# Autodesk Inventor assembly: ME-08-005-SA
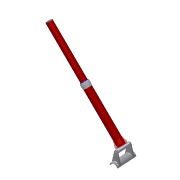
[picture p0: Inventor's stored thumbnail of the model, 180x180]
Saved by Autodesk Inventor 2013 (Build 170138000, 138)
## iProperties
Shininess: 20.0
Length Units: 11269
Angle Units: 11279
Time Units: 11290
Mass Units: 11283
Length Display Precision: 3
Angle Display Precision: 2
Created: 2001-04
Part Number: ME-08-005-SA
Document SubType Name: Baugruppe
Designer: dl
Density: 0.0
Volumn: 0.0
Area: 0.0
PropertySet Name: Model Information
Control State: 0
Master: False
Checked Out: False
Author: dl
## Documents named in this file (14)
- C:\Webworld\Webworld2014\ATC2013\Assemblies\ATC-Baby Carriage\DAMPER\ME-08-005-SA.iam
- C:\Webworld\Webworld2014\ATC2013\Assemblies\ATC-Baby Carriage\DAMPER\Dip_pipe vst.iam
- C:\Webworld\Webworld2014\ATC2013\Assemblies\ATC-Baby Carriage\DAMPER\Spindle vst.iam
- C:\Webworld\Webworld2014\ATC2013\Assemblies\ATC-Baby Carriage\DAMPER\Seam.ipt
- C:\Webworld\Webworld2014\ATC2013\Assemblies\ATC-Baby Carriage\DAMPER\DIN 912 - M5 x 25.ipt
- C:\Webworld\Webworld2014\ATC2013\Assemblies\ATC-Baby Carriage\DAMPER\Spacer_wide.ipt
- C:\Webworld\Webworld2014\ATC2013\Assemblies\ATC-Baby Carriage\DAMPER\Damper_element_big.ipt
- C:\Webworld\Webworld2014\ATC2013\Assemblies\ATC-Baby Carriage\DAMPER\Standpipe vst.iam
- C:\Webworld\Webworld2014\ATC2013\Assemblies\ATC-Baby Carriage\DAMPER\Damper_element_middle.ipt
- C:\Webworld\Webworld2014\ATC2013\Assemblies\ATC-Baby Carriage\DAMPER\Damper_element_small.ipt
- C:\Webworld\Webworld2014\ATC2013\Assemblies\ATC-Baby Carriage\DAMPER\Sliding_disc.ipt
- C:\Webworld\Webworld2014\ATC2013\Assemblies\ATC-Baby Carriage\DAMPER\Bearing_bracket.ipt
- C:\Webworld\Webworld2014\ATC2013\Assemblies\ATC-Baby Carriage\DAMPER\DIN 912 - M6 x 16.ipt
- C:\Webworld\Webworld2014\ATC2013\Assemblies\ATC-Baby Carriage\DAMPER\Plug.ipt
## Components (21 placed, 13 different names)
1. Bearing_bracket:1 — Mate:1
2. Sliding_disc:1 — Insert:9, Mate:2
3. Sliding_disc:2 — Insert:10
4. DIN 912 - M6 x 16:1 — Insert:9
5. DIN 912 - M6 x 16:2 — Insert:10
6. Standpipe vst:1 [sub-assembly]
7. DIN 912 - M5 x 25:1
8. DIN 912 - M5 x 25:2
9. Spindle vst:1 [sub-assembly]
10. Damper_element_small:1
11. Spacer_wide:4 — Insert:4
12. Damper_element_middle:2 — Insert:3, Insert:4
13. Spacer_wide:3 — Insert:2, Insert:3
14. Damper_element_middle:1 — Insert:1, Insert:2
15. Spacer_wide:2 — Insert:1, Bewegung
16. Damper_element_big:1 — Insert:6
17. Spacer_wide:1 — Insert:6, Insert:7, Bewegung
18. Damper_element_big:2 — Insert:7, Insert:8
19. Dip_pipe vst:1 [sub-assembly] — Insert:5, Insert:8
20. Plug:1 — Insert:5
21. Seam:1 — Mate:1, Mate:2
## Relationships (13: Insert 11, Mate 2)
- Insert:1: Damper_element_middle:1 ↔ Spacer_wide:2
- Insert:2: Spacer_wide:3 ↔ Damper_element_middle:1
- Insert:3: Damper_element_middle:2 ↔ Spacer_wide:3
- Insert:4: Spacer_wide:4 ↔ Damper_element_middle:2
- Insert:5: Dip_pipe vst:1 ↔ Plug:1
- Insert:6: Damper_element_big:1 ↔ Spacer_wide:1
- Insert:7: Spacer_wide:1 ↔ Damper_element_big:2
- Insert:8: Damper_element_big:2 ↔ Dip_pipe vst:1
- Bewegung [Insert]: Spacer_wide:2 ↔ Spacer_wide:1
- Insert:9: Sliding_disc:1 ↔ DIN 912 - M6 x 16:1
- Insert:10: Sliding_disc:2 ↔ DIN 912 - M6 x 16:2
- Mate:1: Bearing_bracket:1 ↔ Seam:1
- Mate:2: Sliding_disc:1 ↔ Seam:1
